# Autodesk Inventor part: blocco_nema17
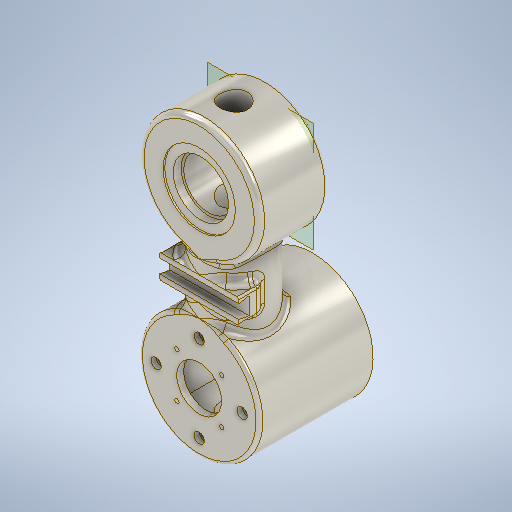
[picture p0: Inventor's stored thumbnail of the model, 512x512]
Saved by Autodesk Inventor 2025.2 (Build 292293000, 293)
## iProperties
Created: 2025-05
Part Number: blocco_nema17
Material: Titanio
Document SubType Name: Modeling
Designer: 18907419
Density: 4.51 g/cm^3
Appearance: Titanio
alezza: 50,000 mm
Author: 18907419
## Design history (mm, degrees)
sketch "Schizzo1"
  geometry: C1 r 35 at (0, 0); 1 further point
  constraints: 1 centre point, 1 coincident
  dimensions: "d0" = 70 diameter of C1
extrude "Estrusione1" new body sketch "Schizzo1" stored distance "d1" = 40; taper "d2" = 0 deg
sketch "Schizzo2"
  geometry: L1 (-35, -20)-(35, -20) reference; L2 (35, 20)-(-35, 20) reference; L3 (35, -20)-(35, 20) reference; L4 (-35, -20)-(-35, 20) reference; C1 r 20 at (0, 0); 1 further point
  constraints: 1 centre point, 1 coincident
  dimensions: "d52" = 40 diameter of C1
extrude "Estrusione2" join sketch "Schizzo2" taper "d4" = 0 deg
sketch "Schizzo7"
  geometry: C1 r 8 at (0, 0); 1 further point
  constraints: 1 centre point, 1 coincident
  dimensions: "d19" = 16 diameter of C1
extrude "Estrusione7" cut sketch "Schizzo7" distance "d20" = 95.5; taper "d21" = 0 deg
sketch "Schizzo12"
  geometry: L1 (-21.05, 21.05)-(21.05, 21.05); L2 (21.05, 21.05)-(21.05, -21.05); L3 (21.05, -21.05)-(-21.05, -21.05); L4 (-21.05, -21.05)-(-21.05, 21.05); L5 (-21.05, 21.05)-(21.05, -21.05); L6 (21.05, 21.05)-(-21.05, -21.05); 1 further point
  constraints: 12 end point, 2 midpoint, 2 parallel, 1 horizontal, 1 perpendicular
  dimensions: "d38" = 42.1 distance of L2.end L3.end; "d39" = 42.1 distance of L1.end L2.end
extrude "Estrusione11" cut sketch "Schizzo12" distance "d40" = 60; taper "d41" = 0 deg
mirror "Speculare2"
sketch "Schizzo13"
  geometry: C1 r 16 at (0, 0); 1 further point
  constraints: 1 centre point
  dimensions: "d42" = 32 diameter of C1
extrude "Estrusione12" cut sketch "Schizzo13" extent not by distance; stored distance "d43" = 32; taper "d44" = 0 deg
mirror "Speculare3"
sketch "Schizzo18"
  geometry: L1 (-21.05, -21.05)-(-21.05, 21.05) reference; L2 (-21.05, 21.05)-(21.05, 21.05) reference; L3 (21.05, 21.05)-(21.05, -21.05) reference; L4 (21.05, -21.05)-(-21.05, -21.05) reference; C1 r 13 at (0, 0); C2 r 1.23 at (13.1, 13.1) reference; C3 r 1.23 at (13.1, -12.9) reference; C4 r 1.23 at (-12.9, -12.9) reference; C5 r 1.23 at (-12.9, 13.1) reference; 3 further points
  constraints: 1 centre point, 1 coincident, 1 vertical alignment
  dimensions: "d63" = 26 diameter of C1
  node "Linea chiusa proiettata5"
  node "Riferimento1"
  node "Riferimento2"
  node "Riferimento3"
  node "Riferimento4"
node "Piano di lavoro2"
extrude "Estrusione16" join sketch "Schizzo18" stored distance "d64" = 3; taper "d65" = 0 deg
sketch "Schizzo19"
  geometry: C1 r 1.7 at (0, 25) reference; 1 further point
hole "Foro3" sketch "Schizzo19" at (0, 25) diameter "d66" = 3.4; stored, may be unused: countersink angle "d70" = 90 deg, drill point angle "d72" = 118 deg; dims "d67" = 6, "d68" = 6.3, "d69" = 3.4, "d71" = 8
sketch "Schizzo20"
  geometry: C1 r 1.7 at (0, 25) reference; 2 further points
  constraints: 1 coincident
hole "Foro4" sketch "Schizzo20" at (0, 25) diameter "d76" = 3.4; stored, may be unused: countersink angle "d80" = 90 deg, drill point angle "d82" = 118 deg; dims "d77" = 6, "d78" = 6, "d79" = 3, "d81" = 8
pattern_circular "Serie circolare2" dims "d84" = 360 deg
fillet "Raccordo2" dims "d88" = 3
fillet "Raccordo3" dims "d89" = 5
fillet "Raccordo4" dims "d90" = 2
fillet "Raccordo5" dims "d91" = 2
node "Piano di lavoro3"
sketch "Schizzo23"
  geometry: L1 (0, 0)-(0, 100); L2 (20, 31.225)-(20, 68.775) reference; L3 (-23, 57)-(23, 57); L4 (23, 57)-(23, 43); L5 (23, 43)-(-23, 43); L6 (-23, 43)-(-23, 57); L7 (-23, 57)-(23, 43); L8 (23, 57)-(-23, 43); C1 r 10.7 at (0, 0) reference; C2 r 16 at (0, 100) reference; 2 further points
  constraints: 14 end point, 3 midpoint, 2 parallel, 1 coincident, 1 horizontal, 1 perpendicular, 1 vertical
  dimensions: "d104" = 46 distance of L4.end L5.end; "d105" = 14 distance of L3.end L4.end
extrude "Estrusione19" join sketch "Schizzo23" distance "d99" = 7; taper "d101" = 0 deg; dims "d100" = 6, "d102" = 0
fillet "Raccordo6" dims "d106" = 5
fillet "Raccordo7" dims "d107" = 5
sketch "Schizzo24"
  geometry: L1 (-10.38, 0)-(-10.38, 14) reference; L2 (-10.38, 0)-(0, 0) reference; L3 (0, 14)-(0, 0) reference; L4 (-10.38, 14)-(0, 14) reference; L5 (0, 7)-(-10.38, 7); L6 (0, 11)-(-6, 12.058); L7 (-6, 12.058)-(-6, 7); L8 (0, 3)-(-6, 1.942); L9 (-6, 1.942)-(-6, 7); L10 (0, 14)-(0, 0) reference; 3 further points
  constraints: 10 end point, 3 midpoint, 2 point on line, 2 symmetric about line, 1 perpendicular
  dimensions: "d108" = 6 distance between parallel lines of L7 L3; "d109" = 80 deg angle of L7 L6; "d113" = 4 distance of point (0, 7) L6.start
extrude "Estrusione20" cut sketch "Schizzo24" extent not by distance; stored distance "d110" = 0; taper "d111" = 0 deg
node "Piano di lavoro4"
sketch "Schizzo25"
  geometry: C1 r 14.5 at (0, 0); C2 r 16 at (0, 0) reference; 1 further point
  constraints: 1 centre point
  dimensions: "d115" = 29 diameter of C1
extrude "Estrusione21" join sketch "Schizzo25" distance "d116" = 30; taper "d117" = 0 deg
sketch "Schizzo26"
  geometry: C1 r 21 at (0, 0); 1 further point
  constraints: 1 centre point
  dimensions: "d118" = 42 diameter of C1
extrude "Estrusione22" cut sketch "Schizzo26" distance "d119" = 1; taper "d120" = 0 deg
fillet "Raccordo9" dims "d121" = 1
fillet "Raccordo10" dims "d122" = 5
sketch "Schizzo27"
  geometry: C1 r 8 at (21.05, 20) reference; C2 r 8 at (21.05, 20); 1 further point
  constraints: 1 centre point, 1 coincident, 1 concentric
extrude "Estrusione23" cut sketch "Schizzo27" extent not by distance; stored distance "d123" = 0; taper "d124" = 0 deg
sketch "Schizzo28"
  geometry: L1 (21.05, 21.05)-(21.05, -21.05) reference; L2 (21.05, -21.05)-(-21.05, -21.05) reference; L3 (-21.05, -21.05)-(-21.05, 21.05) reference; L4 (-21.05, 21.05)-(21.05, 21.05) reference; C1 r 1.7 at (-25, 0) reference; C2 r 1.7 at (0, -25) reference; C3 r 1.7 at (25, 0) reference; C4 r 1.7 at (0, 25) reference; A1 r 35 centre (0, 0) between (0, 35) and (-13.125, 32.446) reference; A2 r 35 centre (0, 0) between (-13.125, 32.446) and (13.125, 32.446) reference; A3 r 35 centre (0, 0) between (13.125, 32.446) and (0, 35) reference; 1 further point
extrude "Estrusione24" join sketch "Schizzo28" distance "d125" = 26; taper "d126" = 0 deg
node "Solido1"
node "Linea chiusa proiettata1"
node "Riferimento5"
node "Riferimento7"
node "Linea chiusa proiettata7"
node "Linea chiusa proiettata8"
other parameters: "d92" = 13, "d114" = -4.5
